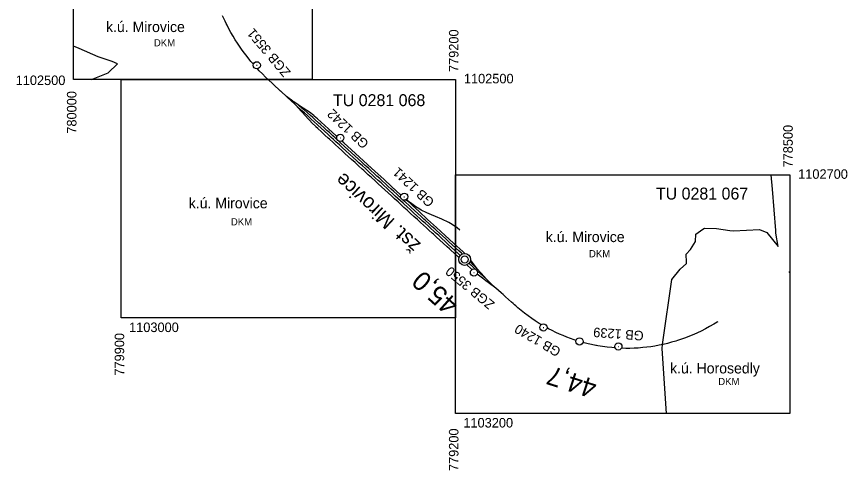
# Model space of a CAD drawing. Extents: x -780362 to -778379, y -1103319 to -1100609.
# Drawn here: x -780119 to -778379, y -1103319 to -1102368 of the extents above; entities that cross this region are included whole.
import ezdxf

# ---------------------------------------------------------------- set-up
doc = ezdxf.new("R2010")
doc.units = 0
for name, color, linetype in [('Vrstva 1', 7, 'Continuous'), ('Vrstva 10', 7, 'Continuous'), ('Vrstva 2', 7, 'Continuous'), ('Vrstva 52', 7, 'Continuous'), ('Vrstva 53', 7, 'Continuous'), ('Vrstva 62', 7, 'Continuous'), ('Vrstva 7', 7, 'Continuous'), ('Vrstva 9', 7, 'Continuous')]:
    doc.layers.add(name, color=color, linetype=linetype)

msp = doc.modelspace()

# ---------------------------------------------------------------- linework, layer by layer
at = {"layer": 'Vrstva 1'}
for p, q in [((-779988.2, -1102435.2), (-780000, -1102430.1)), ((-779948.2, -1102453.1), (-779988.2, -1102435.2)), ((-779927.5, -1102459.8), (-779948.2, -1102453.1)), ((-779919, -1102462.5), (-779927.5, -1102459.8)), ((-779927.5, -1102486.5), (-779907.8, -1102467.2)), ((-779907.8, -1102467.2), (-779919, -1102462.5)), ((-779961.9, -1102500), (-779927.5, -1102486.5)), ((-779539.8, -1102546.1), (-779540.5, -1102545.6)), ((-778536.3, -1102730.1), (-778538.7, -1102700)), ((-778529.4, -1102816.9), (-778536.3, -1102730.1)), ((-778696.6, -1102824.5), (-778682.2, -1102814.1)), ((-778682.2, -1102814.1), (-778678.7, -1102811.6)), ((-778678.7, -1102811.6), (-778653.2, -1102812.2)), ((-778653.2, -1102812.2), (-778625.2, -1102816.4)), ((-778625.2, -1102816.4), (-778617.8, -1102817.5)), ((-778617.8, -1102817.5), (-778563.1, -1102814.9)), ((-778563.1, -1102814.9), (-778548.2, -1102820.8)), ((-778529, -1102822), (-778529.4, -1102816.9)), ((-778697.6, -1102839.7), (-778696.6, -1102824.5)), ((-778548.2, -1102820.8), (-778524, -1102850.2)), ((-778524, -1102850.2), (-778529, -1102822)), ((-778707.7, -1102856.2), (-778697.6, -1102839.7)), ((-778716.6, -1102866.3), (-778707.7, -1102856.2)), ((-778716.1, -1102882.7), (-778716.6, -1102866.3)), ((-778729.4, -1102897.6), (-778716, -1102886.1)), ((-778716, -1102884.4), (-778716.1, -1102882.7)), ((-778716, -1102886.1), (-778716, -1102884.4)), ((-778746.5, -1102919.4), (-778729.4, -1102897.6)), ((-778765.6, -1103050.8), (-778746.5, -1102919.4)), ((-778767.3, -1103063.6), (-778766.3, -1103055.4)), ((-778766.3, -1103055.4), (-778765.6, -1103050.8)), ((-778757.7, -1103200), (-778767.3, -1103063.6))]:
    msp.add_line(p, q, dxfattribs=at)
for points in [[(-779623.2, -1102468.3), (-779626.8, -1102464.1), (-779628.1, -1102462.6), (-779630.4, -1102459.7), (-779636.2, -1102452.4), (-779641.6, -1102445.4), (-779646.6, -1102438.5), (-779652, -1102430.7), (-779656.5, -1102424.1), (-779661, -1102417), (-779665.4, -1102409.8), (-779670, -1102401.9), (-779674.3, -1102394.1), (-779678.3, -1102386.5), (-779680.2, -1102382.8), (-779682.3, -1102378.4), (-779684.3, -1102374.1), (-779687.7, -1102366.6)], [(-779566.2, -1102524.6), (-779569.1, -1102521.9), (-779570.3, -1102520.8), (-779577.2, -1102514.5), (-779583.9, -1102508.2), (-779590.7, -1102501.8), (-779597.5, -1102495.3), (-779604.1, -1102488.7), (-779610.7, -1102481.9), (-779614.4, -1102477.9)], [(-779541.7, -1102547), (-779553.9, -1102535.8), (-779565, -1102525.7), (-779565.8, -1102524.9), (-779566.2, -1102524.6)], [(-779540.5, -1102545.6), (-779553.9, -1102535.8), (-779565, -1102525.7), (-779565.8, -1102524.9), (-779566.2, -1102524.6)], [(-779522, -1102564.9), (-779533.9, -1102554.1), (-779540.7, -1102547.9), (-779541.7, -1102547)], [(-779523.2, -1102566.3), (-779533.9, -1102554.1), (-779540.7, -1102547.9), (-779541.7, -1102547)], [(-779518.9, -1102560.3), (-779529.6, -1102553.6), (-779538.7, -1102546.9), (-779539.6, -1102546.3), (-779539.8, -1102546.1)], [(-779519.9, -1102561.6), (-779529.6, -1102553.6), (-779538.7, -1102546.9), (-779539.6, -1102546.3), (-779539.8, -1102546.1)], [(-779192.6, -1102873.5), (-779194, -1102872.2), (-779195.3, -1102871), (-779202.5, -1102864.4), (-779209.8, -1102857.8), (-779212.5, -1102855.3), (-779217, -1102851.2), (-779225.7, -1102843.2), (-779232.7, -1102836.9), (-779239.7, -1102830.5), (-779246.1, -1102824.6), (-779249, -1102822), (-779255.4, -1102816.1), (-779260.5, -1102811.4), (-779266.7, -1102805.7), (-779273.3, -1102799.7), (-779279.6, -1102793.9), (-779286.8, -1102787.3), (-779293.8, -1102781), (-779300.9, -1102774.4), (-779307.8, -1102768.2), (-779314.1, -1102762.4), (-779320.1, -1102756.8), (-779327.3, -1102750.3), (-779334.1, -1102744.1), (-779340.9, -1102737.9), (-779347.5, -1102731.8), (-779354.7, -1102725.2), (-779361.8, -1102718.7), (-779369, -1102712.1), (-779376, -1102705.7), (-779382.5, -1102699.7), (-779389.2, -1102693.7), (-779392.1, -1102691), (-779395.2, -1102688.1), (-779403, -1102681), (-779410.3, -1102674.3), (-779417.4, -1102667.8), (-779424.4, -1102661.4), (-779431.5, -1102655), (-779438.2, -1102648.8), (-779444.8, -1102642.8), (-779451.3, -1102636.9), (-779456.3, -1102632.4), (-779463.7, -1102625.6), (-779466.3, -1102623.2), (-779473.4, -1102616.7), (-779480.7, -1102610.1), (-779488.3, -1102603), (-779492.1, -1102599.3), (-779493.2, -1102598.2), (-779499.9, -1102591.5), (-779505.9, -1102585.2), (-779507.4, -1102583.6), (-779514.5, -1102576), (-779520.4, -1102569.4), (-779523.2, -1102566.3)], [(-779189.9, -1102868.9), (-779195.3, -1102864), (-779201.5, -1102858.3), (-779208.3, -1102852.1), (-779215, -1102845.9), (-779221.8, -1102839.7), (-779228.6, -1102833.5), (-779235.1, -1102827.5), (-779241.9, -1102821.3), (-779245.4, -1102818.1), (-779251.3, -1102812.7), (-779257.3, -1102807.2), (-779263.5, -1102801.6), (-779268.7, -1102796.8), (-779274.3, -1102791.7), (-779280.9, -1102785.7), (-779287.5, -1102779.6), (-779294.8, -1102772.9), (-779301.2, -1102767), (-779308, -1102760.9), (-779308.9, -1102760), (-779309.7, -1102759.4), (-779314.8, -1102754.6), (-779320.4, -1102749.5), (-779326, -1102744.4), (-779331.6, -1102739.3), (-779338, -1102733.4), (-779343.9, -1102728), (-779349.9, -1102722.5), (-779355.8, -1102717.1), (-779361.8, -1102711.6), (-779367.8, -1102706.2), (-779373.7, -1102700.7), (-779379.7, -1102695.3), (-779384.2, -1102691.2), (-779384.9, -1102690.5), (-779388.6, -1102687.1), (-779394.9, -1102681.3), (-779402.2, -1102674.7), (-779407.4, -1102670), (-779414, -1102663.8), (-779421.8, -1102656.8), (-779429.2, -1102650), (-779436.2, -1102643.6), (-779443.1, -1102637.3), (-779450.1, -1102630.8), (-779455.1, -1102626.2), (-779460.1, -1102621.6), (-779467.3, -1102615.1), (-779474.5, -1102608.4), (-779481.4, -1102602.1), (-779488, -1102596.1), (-779488.8, -1102595.4), (-779489.6, -1102594.6), (-779495.6, -1102589), (-779501.9, -1102583.4), (-779509.4, -1102576.5), (-779516.2, -1102570.3), (-779519.6, -1102567.1), (-779522, -1102564.9)], [(-779447.3, -1102626.9), (-779452.1, -1102622.5), (-779456.7, -1102618.3), (-779464, -1102611.6), (-779469.2, -1102606.8), (-779475.2, -1102601.3), (-779482.4, -1102594.8), (-779485.9, -1102591.6), (-779486.6, -1102591), (-779493.4, -1102584.7), (-779498.7, -1102579.9), (-779503.2, -1102575.8), (-779510.2, -1102569.7), (-779516.9, -1102564.1), (-779519.9, -1102561.6)], [(-779488.9, -1102582.4), (-779495.6, -1102576.8), (-779496.7, -1102575.9), (-779505.9, -1102569), (-779518.9, -1102560.3)], [(-779448.2, -1102619.8), (-779449.9, -1102618.2), (-779465.8, -1102603.6), (-779481.1, -1102589.5), (-779488.9, -1102582.4)], [(-779314.4, -1102748.4), (-779317.1, -1102745.9), (-779322.8, -1102740.7), (-779328.7, -1102735.3), (-779334.7, -1102729.8), (-779340.6, -1102724.4), (-779346.6, -1102719), (-779352.6, -1102713.5), (-779358.5, -1102708), (-779364.5, -1102702.6), (-779370.4, -1102697.1), (-779376.4, -1102691.7), (-779380.9, -1102687.6), (-779381.6, -1102686.9), (-779385.5, -1102683.4), (-779388.9, -1102680.3), (-779396.3, -1102673.5), (-779403.8, -1102666.6), (-779410.6, -1102660.4), (-779417.9, -1102653.7), (-779425.1, -1102647.1), (-779432.5, -1102640.4), (-779439.7, -1102633.8), (-779444.9, -1102629.1)], [(-779313.9, -1102742.4), (-779315.5, -1102740.9), (-779332.9, -1102725), (-779350.2, -1102709.2), (-779367.9, -1102693), (-779384.1, -1102678.2), (-779401.2, -1102662.7), (-779417.6, -1102647.8), (-779434, -1102632.8), (-779437.8, -1102629.3)], [(-779185.7, -1102865.9), (-779186.4, -1102865.2), (-779187.3, -1102864.4), (-779193.1, -1102859.1), (-779200.1, -1102852.7), (-779206.7, -1102846.7), (-779213.6, -1102840.4), (-779220.1, -1102834.4), (-779227, -1102828.2), (-779233.6, -1102822.1), (-779239.9, -1102816.4), (-779243.4, -1102813.2), (-779249.1, -1102808), (-779255.6, -1102802.1), (-779262.4, -1102795.8), (-779266, -1102792.6), (-779271.9, -1102787.2), (-779278.8, -1102780.9), (-779285.8, -1102774.5), (-779292.5, -1102768.4), (-779297.8, -1102763.5), (-779304.1, -1102757.8), (-779305.6, -1102756.4), (-779306.3, -1102755.7), (-779309.1, -1102753.3)], [(-779290, -1102764.2), (-779290.6, -1102763.7), (-779292.1, -1102762.3), (-779301, -1102754.1), (-779302.5, -1102752.8), (-779303.1, -1102752.3)], [(-779288.5, -1102762.9), (-779291.1, -1102761), (-779303, -1102752.2)], [(-779183.7, -1102861.7), (-779204, -1102843), (-779221.3, -1102827.2), (-779239.5, -1102810.5), (-779258.3, -1102793.3), (-779276.2, -1102776.8), (-779290, -1102764.2)], [(-779190.5, -1102816), (-779196.3, -1102811.4), (-779199.5, -1102809), (-779201.6, -1102807.5), (-779204.9, -1102805.2), (-779210.1, -1102801.9), (-779213.6, -1102799.9), (-779228.7, -1102792.6), (-779241.8, -1102787.3), (-779250.4, -1102783.9), (-779260, -1102779.8), (-779271.8, -1102773.8), (-779274.5, -1102772.3), (-779282.9, -1102766.9), (-779288.5, -1102762.9)], [(-779180.4, -1102864.9), (-779183.7, -1102861.7)], [(-779158.2, -1102897.9), (-779158.7, -1102897.4), (-779163.8, -1102892.7), (-779170.3, -1102886.8), (-779171.5, -1102885.7)], [(-779163.3, -1102887.8), (-779166.4, -1102884.5), (-779169.1, -1102881.8)], [(-779162, -1102886.7), (-779168.3, -1102878.2)], [(-779146.2, -1102906.4), (-779147, -1102905.5), (-779154.6, -1102896.9), (-779163.3, -1102887.8)], [(-779146.2, -1102906.4), (-779147, -1102905.5), (-779154.6, -1102896.9), (-779162, -1102886.7)], [(-779165.3, -1102898.5), (-779167.8, -1102896.3), (-779175.1, -1102889.6), (-779175.9, -1102888.8)], [(-779147.5, -1102907.7), (-779153.8, -1102901.9), (-779154.6, -1102901.2)], [(-778500, -1102903.3), (-778501.8, -1102904.5)], [(-779128.6, -1102927.4), (-779136.4, -1102921.8), (-779143.4, -1102916.7), (-779148.8, -1102912.5), (-779154.4, -1102908)], [(-779127.5, -1102926), (-779127.8, -1102925.7), (-779128.4, -1102925.2), (-779135.2, -1102918.9), (-779147.5, -1102907.7)], [(-779127.5, -1102926), (-779127.8, -1102925.7), (-779128.4, -1102925.2), (-779135.2, -1102918.9), (-779146.2, -1102906.4)], [(-779103, -1102948.5), (-779103.7, -1102947.8), (-779104.1, -1102947.4), (-779115.2, -1102937.2), (-779128.6, -1102927.4)], [(-779103, -1102948.5), (-779103.7, -1102947.8), (-779104.1, -1102947.4), (-779115.2, -1102937.2), (-779127.5, -1102926)], [(-779020.3, -1103013.8), (-779024.6, -1103011.2), (-779032.7, -1103006.1), (-779040.1, -1103001.1), (-779047.8, -1102995.6), (-779055.1, -1102990.1), (-779062.4, -1102984.3), (-779069.2, -1102978.6), (-779073.8, -1102974.6), (-779076.1, -1102972.7), (-779079.3, -1102969.9), (-779082.8, -1102966.7), (-779089.2, -1102961), (-779095.2, -1102955.6), (-779099.5, -1102951.6), (-779100.3, -1102950.9), (-779103.7, -1102947.8)], [(-778650.8, -1103008), (-778651.8, -1103008.6), (-778658.8, -1103012.9), (-778667.7, -1103018.1), (-778676.6, -1103023), (-778685.6, -1103027.6), (-778692.9, -1103031.1), (-778700.7, -1103034.6), (-778709.8, -1103038.4), (-778718.1, -1103041.6), (-778726.9, -1103044.7), (-778734.9, -1103047.4), (-778738.5, -1103048.5), (-778747.2, -1103051), (-778755.8, -1103053.3), (-778765, -1103055.4), (-778773.5, -1103057.2), (-778782.4, -1103058.8), (-778791.1, -1103060.2), (-778799.5, -1103061.3), (-778807.6, -1103062.1), (-778817.1, -1103062.9), (-778825.8, -1103063.3), (-778835, -1103063.6), (-778843.5, -1103063.6), (-778852.3, -1103063.4)], [(-778947.4, -1103046.9), (-778951.4, -1103045.6), (-778959, -1103042.9), (-778966.5, -1103040.1), (-778974.2, -1103037), (-778982.1, -1103033.7), (-778989.7, -1103030.2), (-778997.3, -1103026.5), (-779005.3, -1103022.4), (-779008.2, -1103020.8)], [(-778865.7, -1103062.7), (-778872.8, -1103062.1), (-778882.4, -1103061.1), (-778891.9, -1103059.8), (-778901.5, -1103058.3), (-778904.3, -1103057.7), (-778905.9, -1103057.4), (-778914.9, -1103055.6), (-778922.3, -1103053.9), (-778930.6, -1103051.8), (-778933, -1103051.1)]]:
    msp.add_lwpolyline(points, dxfattribs=at)
at = {"layer": 'Vrstva 2'}
for points in [[(-779541.7, -1102547), (-779540.8, -1102547.8)], [(-779303, -1102752.2), (-779288.6, -1102762.9)]]:
    msp.add_lwpolyline(points, dxfattribs=at)
at = {"layer": 'Vrstva 52'}
for p, q in [((-779616.5, -1102470.5), (-779615.5, -1102470.5)), ((-779441.6, -1102622.5), (-779440.6, -1102622.5)), ((-779307.7, -1102745.9), (-779306.7, -1102745.9)), ((-779161.7, -1102904.8), (-779160.7, -1102904.8)), ((-779016.2, -1103019.8), (-779015.2, -1103019.8)), ((-778859.3, -1103059.6), (-778858.3, -1103059.6))]:
    msp.add_line(p, q, dxfattribs=at)
for centre in [(-779616, -1102470.5), (-779441.1, -1102622.5), (-779307.2, -1102745.9), (-779161.2, -1102904.8), (-779015.7, -1103019.8), (-778858.8, -1103059.6)]:
    msp.add_circle(centre, 7.56, dxfattribs=at)
at = {"layer": 'Vrstva 62'}
for points in [[(-780000, -1101800), (-779500, -1101800), (-779500, -1102500), (-780000, -1102500), (-780000, -1101800)], [(-779900, -1103000), (-779900, -1102500), (-779200, -1102500), (-779200, -1103000), (-779900, -1103000)], [(-779200, -1103200), (-779200, -1102700), (-778500, -1102700), (-778500, -1103200), (-779200, -1103200)]]:
    msp.add_lwpolyline(points, dxfattribs=at)
for radius in [12.5, 7.52]:
    msp.add_circle((-779180.7, -1102877.3), radius, dxfattribs=at)
at = {"layer": 'Vrstva 7'}
msp.add_circle((-778940.2, -1103049.1), 7.5, dxfattribs=at)

# ---------------------------------------------------------------- texts
at = {"layer": 'Vrstva 10'}
for p in [(-779831.5, -1102430.8), (-779670.2, -1102805.9), (-778920.4, -1102872.8), (-778649.7, -1103140.6)]:
    msp.add_text('DKM', height=15, dxfattribs=at).set_placement(p)
at = {"layer": 'Vrstva 53'}
for s, rotation, p in [('ZGB 3551', 130.1607, (-779544, -1102484.4)), ('GB 1242', 136.7912, (-779379.8, -1102632.6)), ('GB 1241', 136.7912, (-779242.5, -1102755)), ('ZGB 3550', 140.3113, (-779116.4, -1102968.5)), ('GB 1240', 149.6352, (-778977.3, -1103065.1)), ('GB 1239', 175.7814, (-778805.2, -1103027.6))]:
    msp.add_text(s, height=20, rotation=rotation, dxfattribs=at).set_placement(p)
at = {"layer": 'Vrstva 62'}
for s, height, rotation, p in [('779200', 20, 90, (-779193.6, -1102484.6)), ('780000', 20, 90, (-779993.6, -1102613.8)), ('778500', 20, 90, (-778493.6, -1102684.6)), ('žst. Mirovice', 30, 137.3125, (-779270.9, -1102844.5)), ('45,0', 40, 138.2804, (-779190.5, -1102967.4)), ('779900', 20, 90, (-779893.6, -1103120.7)), ('44,7', 40, 162.1663, (-778900.9, -1103131.4)), ('779200', 20, 90, (-779193.6, -1103320.7))]:
    msp.add_text(s, height=height, rotation=rotation, dxfattribs=at).set_placement(p)
for s, height, p in [('1102500', 20, (-779182.3, -1102508.4)), ('1102500', 20, (-780120.9, -1102511.9)), ('TU 0281 068', 25, (-779456.4, -1102556.1)), ('1102700', 20, (-778482.3, -1102708.4)), ('TU 0281 067', 25, (-778780.2, -1102751.8)), ('1103000', 20, (-779883.4, -1103029.5)), ('1103200', 20, (-779183.4, -1103229.5))]:
    msp.add_text(s, height=height, dxfattribs=at).set_placement(p)
at = {"layer": 'Vrstva 9'}
for s, p in [('k.ú. Mirovice', (-779931.7, -1102400.9)), ('k.ú. Mirovice', (-779758.4, -1102770.2)), ('k.ú. Mirovice', (-779010.8, -1102841)), ('k.ú. Horosedly', (-778750.6, -1103116.2))]:
    msp.add_text(s, height=22, dxfattribs=at).set_placement(p)

doc.saveas('drawing.dxf')
